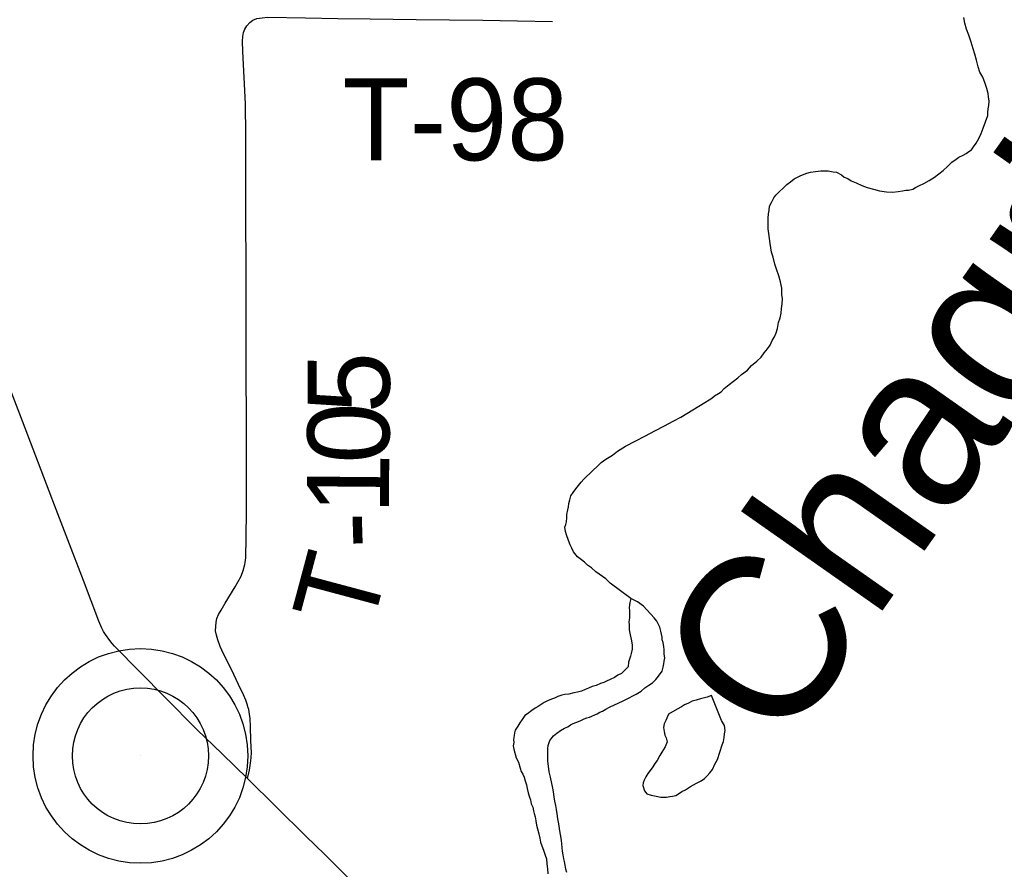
# Model space of a CAD drawing. Extents: x -11.4 to 84.1, y 11.1 to 59.
# Drawn here: x 30.516 to 31.198, y 46.042 to 46.631 of the extents above; entities that cross this region are included whole.
import ezdxf

# ---------------------------------------------------------------- set-up
doc = ezdxf.new("R2010")
doc.units = 0
for name, color, linetype in [('GM_X_County_Road', 7, 'Continuous'), ('GM_X_Major_River', 7, 'Continuous'), ('GM_X_Major_River_Text', 7, 'Continuous'), ('GM_X_Minor_Lake', 7, 'Continuous'), ('GM_X_Township_Road', 7, 'Continuous'), ('GM_X_Township_Road_Text', 7, 'Continuous'), ('GM_X_Unincorporated', 7, 'Continuous'), ('GM_X_Unincorporated_Location', 7, 'Continuous')]:
    doc.layers.add(name, color=color, linetype=linetype)

msp = doc.modelspace()

# ---------------------------------------------------------------- linework, layer by layer
at = {"layer": 'GM_X_County_Road'}
for points in [[(30.53861, 46.29722), (30.5379, 46.29909), (30.5268, 46.32812), (30.51571, 46.35714), (30.50463, 46.38616)], [(30.67345, 46.10475), (30.65588, 46.12173), (30.63832, 46.13872), (30.61646, 46.1608), (30.59888, 46.17856), (30.5813, 46.19632), (30.5796, 46.19824), (30.57799, 46.20026), (30.5751, 46.20449), (30.57377, 46.2067), (30.57259, 46.20897), (30.57056, 46.21368), (30.55977, 46.24187), (30.54898, 46.27007), (30.53861, 46.29722)], [(30.81127, 45.9465), (30.80276, 45.96043), (30.79284, 45.9753), (30.78345, 45.98887), (30.77331, 46.00193), (30.76253, 46.01486), (30.75162, 46.02704), (30.74071, 46.03846), (30.7272, 46.05177), (30.71369, 46.06508), (30.69357, 46.08492), (30.67345, 46.10475)]]:
    msp.add_lwpolyline(points, dxfattribs=at)
at = {"layer": 'GM_X_Major_River'}
for points in [[(31.06089, 46.52418), (31.06353, 46.52499), (31.06694, 46.52542), (31.07073, 46.52586), (31.07567, 46.52594), (31.0791, 46.52524), (31.08139, 46.5249), (31.08483, 46.52305), (31.08676, 46.52156), (31.08943, 46.52046), (31.09174, 46.51898), (31.09518, 46.51752), (31.09901, 46.51568), (31.10283, 46.51422), (31.10703, 46.51315), (31.11123, 46.51208), (31.11618, 46.5114), (31.12036, 46.51109), (31.12415, 46.51153), (31.12718, 46.51196), (31.12945, 46.51238), (31.13135, 46.51241), (31.13438, 46.51322), (31.13626, 46.51439), (31.1389, 46.51557), (31.14191, 46.51714), (31.14567, 46.51911), (31.14943, 46.52145), (31.15243, 46.52378), (31.15543, 46.52611), (31.15843, 46.52882), (31.16141, 46.53191), (31.16442, 46.53386), (31.16629, 46.53542), (31.16931, 46.53661), (31.17119, 46.53778), (31.17306, 46.53933), (31.17494, 46.5405), (31.17643, 46.54243), (31.17828, 46.54512), (31.18013, 46.54819), (31.18159, 46.55164), (31.18305, 46.55546), (31.18632, 46.56426), (31.18629, 46.56617), (31.18662, 46.56883), (31.18696, 46.57112), (31.18729, 46.57417), (31.18686, 46.5772), (31.18644, 46.57948), (31.18563, 46.58289), (31.18443, 46.58629), (31.18283, 46.59083), (31.18088, 46.59422), (31.17968, 46.598), (31.17846, 46.60254), (31.17725, 46.60671), (31.17605, 46.61049), (31.17483, 46.61503), (31.17323, 46.61995), (31.17164, 46.6241), (31.17043, 46.62827), (31.16961, 46.63206)], [(30.93898, 46.22937), (30.92473, 46.24017), (30.92164, 46.24316), (30.91472, 46.24799), (30.91164, 46.2506), (30.90895, 46.25246), (30.90701, 46.25471), (30.90471, 46.25619), (30.90201, 46.25843), (30.8993, 46.26181), (30.89812, 46.26445), (30.89694, 46.26671), (30.89575, 46.26974), (30.89454, 46.27352), (30.89375, 46.27579), (30.89332, 46.27882), (30.89404, 46.28074), (30.89439, 46.28264), (30.89473, 46.28531), (30.89469, 46.28759), (30.89539, 46.29102), (30.89574, 46.29293), (30.89608, 46.29522), (30.89679, 46.29789), (30.89751, 46.30057), (30.89899, 46.30287), (30.90084, 46.30556), (30.90271, 46.30788), (30.90457, 46.31019), (30.90643, 46.31212), (30.9083, 46.31405), (30.91054, 46.31599), (30.91279, 46.31831), (30.91578, 46.32102), (30.91839, 46.32373), (30.92177, 46.32606), (30.92628, 46.3288), (30.92966, 46.33152), (30.93529, 46.33503), (30.94207, 46.33856), (30.94923, 46.3421), (30.95563, 46.34563), (30.9624, 46.34916), (30.96843, 46.35231), (30.9737, 46.35505), (30.9861, 46.36286), (30.99024, 46.36521), (30.99325, 46.36716), (30.99513, 46.36833), (30.997, 46.36988), (30.99963, 46.37145), (31.00151, 46.37262), (31.00375, 46.37494), (31.00713, 46.37766), (31.01013, 46.37999), (31.01313, 46.38232), (31.01575, 46.38464), (31.01987, 46.38775), (31.02248, 46.39084), (31.02622, 46.39394), (31.02922, 46.39665), (31.03145, 46.39973), (31.03368, 46.40243), (31.03553, 46.40512), (31.037, 46.40819), (31.03848, 46.41087), (31.03957, 46.41356), (31.04066, 46.41661), (31.04135, 46.42081), (31.04243, 46.42387), (31.04314, 46.4273), (31.04347, 46.43035), (31.04379, 46.43378), (31.04411, 46.4372), (31.04368, 46.44024), (31.04361, 46.44442), (31.04278, 46.44897), (31.04157, 46.45313), (31.03997, 46.45767), (31.03877, 46.46107), (31.03755, 46.466), (31.03636, 46.4694), (31.03593, 46.47243), (31.0355, 46.47547), (31.03506, 46.47888), (31.03462, 46.4823), (31.03418, 46.48571), (31.03413, 46.48914), (31.03406, 46.49294), (31.03439, 46.49599), (31.03473, 46.49827), (31.03506, 46.50132), (31.03654, 46.50401), (31.038, 46.50707), (31.03949, 46.509), (31.04696, 46.51635), (31.04959, 46.51829), (31.05222, 46.52024), (31.05485, 46.5218), (31.05673, 46.52259), (31.06089, 46.52418)], [(30.89467, 46.03966), (30.89387, 46.04193), (30.89344, 46.04458), (30.89302, 46.04724), (30.89261, 46.04913), (30.89218, 46.05179), (30.89176, 46.05444), (30.89134, 46.05672), (30.8913, 46.05938), (30.89088, 46.06165), (30.89045, 46.06469), (30.89003, 46.06696), (30.8896, 46.07), (30.88916, 46.07341), (30.88835, 46.07682), (30.88791, 46.08024), (30.88748, 46.08327), (30.88705, 46.08592), (30.88624, 46.08895), (30.88581, 46.09199), (30.88537, 46.09541), (30.88495, 46.09806), (30.8833, 46.10564), (30.88289, 46.10753), (30.88248, 46.10943), (30.88204, 46.11322), (30.8816, 46.11664), (30.88156, 46.1193), (30.8815, 46.12234), (30.88146, 46.12538), (30.8818, 46.12767), (30.88288, 46.13111), (30.88548, 46.13419), (30.88773, 46.13613), (30.89036, 46.13808), (30.89299, 46.13964), (30.89525, 46.14044), (30.89713, 46.14199), (30.89901, 46.14278), (30.9009, 46.14357), (30.90392, 46.14476), (30.90656, 46.14595), (30.90844, 46.14674), (30.91034, 46.14715), (30.91561, 46.14952), (30.91749, 46.15069), (30.91938, 46.15148), (30.92164, 46.15266), (30.92427, 46.15422), (30.93369, 46.15856), (30.93558, 46.15935), (30.93784, 46.16053), (30.94047, 46.16209), (30.94273, 46.16327), (30.94611, 46.16523), (30.94874, 46.16755), (30.95136, 46.1695), (30.954, 46.17106), (30.95624, 46.17338), (30.9581, 46.17569), (30.9607, 46.17916), (30.96141, 46.18183), (30.96175, 46.18412), (30.9621, 46.18602), (30.96244, 46.18831), (30.96202, 46.19097), (30.96197, 46.19401), (30.96193, 46.19591), (30.9615, 46.19895), (30.96071, 46.20083), (30.96068, 46.20273), (30.96027, 46.20463), (30.95985, 46.2069), (30.95905, 46.20955), (30.95826, 46.21144), (30.95708, 46.2137), (30.95514, 46.21595), (30.94779, 46.2242), (30.94356, 46.22717), (30.94087, 46.22865), (30.93898, 46.22937)], [(30.93898, 46.22937), (30.93825, 46.2267), (30.93793, 46.22327), (30.93797, 46.22099), (30.93801, 46.21833), (30.93805, 46.21605), (30.93771, 46.21338), (30.93775, 46.2111), (30.93781, 46.20768), (30.93862, 46.20427), (30.93945, 46.2001), (30.93989, 46.19707), (30.93993, 46.19441), (30.93922, 46.19135), (30.93887, 46.18945), (30.93815, 46.18753), (30.93743, 46.18524), (30.9371, 46.18219), (30.93523, 46.18026), (30.93261, 46.17756)], [(30.93261, 46.17756), (30.92998, 46.17637), (30.92772, 46.17481), (30.92471, 46.17324), (30.92207, 46.17206), (30.92019, 46.17127), (30.91792, 46.17047), (30.9149, 46.16928), (30.91226, 46.16848), (30.90962, 46.16729), (30.90735, 46.16649), (30.90472, 46.16531), (30.90207, 46.16451), (30.89942, 46.16408), (30.89601, 46.16327), (30.89336, 46.16284), (30.89109, 46.16242), (30.88844, 46.16162), (30.88618, 46.16044), (30.88392, 46.15965), (30.88128, 46.15846), (30.87902, 46.15728), (30.87489, 46.15455), (30.87263, 46.15338), (30.87038, 46.15182), (30.86738, 46.14949), (30.8655, 46.14832), (30.86364, 46.14562), (30.86216, 46.14332), (30.86068, 46.14101), (30.85883, 46.13832), (30.85848, 46.13641), (30.85813, 46.13451), (30.8578, 46.13184), (30.85783, 46.12956), (30.85749, 46.12727), (30.85791, 46.12499), (30.85953, 46.11894), (30.8611, 46.11592), (30.86231, 46.11176), (30.86311, 46.10949), (30.86428, 46.10761), (30.86507, 46.10572), (30.86588, 46.10307), (30.86668, 46.10042), (30.86711, 46.09777), (30.86791, 46.09474), (30.86872, 46.09171), (30.86952, 46.08982), (30.86994, 46.08717), (30.87112, 46.0849), (30.87154, 46.08225), (30.87195, 46.08035), (30.87275, 46.07809), (30.87318, 46.07543), (30.87361, 46.0724), (30.87441, 46.06975), (30.87523, 46.06634), (30.87604, 46.06331), (30.87646, 46.06065), (30.87727, 46.05801), (30.87846, 46.05498), (30.87965, 46.05158), (30.88046, 46.04893), (30.8809, 46.04552), (30.88133, 46.0421), (30.88139, 46.03868)]]:
    msp.add_lwpolyline(points, dxfattribs=at)
at = {"layer": 'GM_X_Minor_Lake'}
for points in [[(30.94721, 46.09984), (30.94842, 46.09606), (30.94997, 46.09418), (30.95302, 46.09309), (30.95645, 46.09239), (30.95988, 46.09168), (30.96368, 46.09175), (30.96595, 46.09216), (30.96785, 46.09257), (30.97012, 46.09299), (30.972, 46.09417), (30.97425, 46.09572), (30.97689, 46.09691), (30.98027, 46.09924), (30.9844, 46.10159), (30.9878, 46.10317), (30.99005, 46.10473), (30.99192, 46.10666), (30.99378, 46.10859), (30.99565, 46.1109), (30.9971, 46.11473), (30.99895, 46.1178), (31.00219, 46.12812), (31.00329, 46.13042), (31.00363, 46.13309), (31.00397, 46.13576), (31.00431, 46.13805), (31.00387, 46.14146), (31.00191, 46.14485), (30.99479, 46.16223)], [(30.99479, 46.16223), (30.99176, 46.16103), (30.98723, 46.15982), (30.9842, 46.15901), (30.98156, 46.15821), (30.97892, 46.15702), (30.97628, 46.15584), (30.97403, 46.15428), (30.97101, 46.15271), (30.965, 46.14919), (30.96317, 46.14498), (30.96207, 46.14267), (30.96173, 46.14001), (30.96216, 46.13735), (30.96258, 46.1347), (30.96337, 46.13281), (30.96418, 46.13016), (30.96272, 46.12671), (30.96161, 46.1248), (30.9605, 46.12288), (30.95902, 46.12057), (30.95718, 46.11712), (30.95569, 46.11519), (30.95421, 46.11289), (30.95236, 46.11019), (30.95087, 46.10827), (30.94939, 46.10596), (30.94829, 46.10366), (30.94756, 46.10175), (30.94721, 46.09984)], [(30.99479, 46.16223), (30.99176, 46.16103), (30.98723, 46.15982), (30.9842, 46.15901), (30.98156, 46.15821), (30.97892, 46.15702), (30.97628, 46.15584), (30.97403, 46.15428), (30.97101, 46.15271), (30.965, 46.14919), (30.96317, 46.14498), (30.96207, 46.14267), (30.96173, 46.14001), (30.96216, 46.13735), (30.96258, 46.1347), (30.96337, 46.13281), (30.96418, 46.13016), (30.96272, 46.12671), (30.96161, 46.1248), (30.9605, 46.12288), (30.95902, 46.12057), (30.95718, 46.11712), (30.95569, 46.11519), (30.95421, 46.11289), (30.95236, 46.11019), (30.95087, 46.10827), (30.94939, 46.10596), (30.94829, 46.10366), (30.94756, 46.10175), (30.94721, 46.09984), (30.94842, 46.09606), (30.94997, 46.09418), (30.95302, 46.09309), (30.95645, 46.09239), (30.95988, 46.09168), (30.96368, 46.09175), (30.96595, 46.09216), (30.96785, 46.09257), (30.97012, 46.09299), (30.972, 46.09417), (30.97425, 46.09572), (30.97689, 46.09691), (30.98027, 46.09924), (30.9844, 46.10159), (30.9878, 46.10317), (30.99005, 46.10473), (30.99192, 46.10666), (30.99378, 46.10859), (30.99565, 46.1109), (30.9971, 46.11473), (30.99895, 46.1178), (31.00219, 46.12812), (31.00329, 46.13042), (31.00363, 46.13309), (31.00397, 46.13576), (31.00431, 46.13805), (31.00387, 46.14146), (31.00191, 46.14485), (30.99479, 46.16223)]]:
    msp.add_lwpolyline(points, dxfattribs=at)
at = {"layer": 'GM_X_Township_Road'}
for points in [[(30.66904, 46.24486), (30.67047, 46.24875), (30.67161, 46.25306), (30.67191, 46.25433), (30.67217, 46.25755), (30.67238, 46.26229), (30.67255, 46.2672), (30.67267, 46.29456), (30.67281, 46.31643), (30.67239, 46.52948), (30.67225, 46.55089), (30.6721, 46.57231), (30.67114, 46.59048), (30.67018, 46.60866), (30.66998, 46.61566), (30.67019, 46.61904), (30.67061, 46.62169), (30.67153, 46.62408), (30.67305, 46.62636), (30.67514, 46.62865)], [(30.67514, 46.62865), (30.67723, 46.63026), (30.67999, 46.63131), (30.68361, 46.63198), (30.6876, 46.63226), (30.71373, 46.63184), (30.73611, 46.63146), (30.7585, 46.63107), (30.77442, 46.63095), (30.79033, 46.63082), (30.81336, 46.63053), (30.83638, 46.63024), (30.86054, 46.62983), (30.88469, 46.62942)], [(30.53861, 46.29722), (30.5379, 46.29909), (30.5268, 46.32812), (30.51571, 46.35714), (30.50463, 46.38616)], [(30.67345, 46.10475), (30.65588, 46.12173), (30.63832, 46.13872), (30.61646, 46.1608), (30.59888, 46.17856), (30.5813, 46.19632), (30.5796, 46.19824), (30.57799, 46.20026), (30.5751, 46.20449), (30.57377, 46.2067), (30.57259, 46.20897), (30.57056, 46.21368), (30.55977, 46.24187), (30.54898, 46.27007), (30.53861, 46.29722)], [(30.67378, 46.15437), (30.67342, 46.15558), (30.67217, 46.15898), (30.67056, 46.16264), (30.66717, 46.16988), (30.66234, 46.18025), (30.6568, 46.19106), (30.65457, 46.19624), (30.65296, 46.2008), (30.65197, 46.20402), (30.65138, 46.2071), (30.65171, 46.21296), (30.65225, 46.21555), (30.65341, 46.21832), (30.6551, 46.22126), (30.65785, 46.22612), (30.66493, 46.23745), (30.66904, 46.24486)], [(30.67345, 46.10475), (30.67476, 46.11045), (30.6756, 46.11527), (30.67593, 46.11894), (30.67611, 46.1227), (30.67586, 46.13075), (30.67552, 46.14066), (30.67521, 46.1462), (30.67485, 46.1494), (30.67432, 46.15254), (30.67378, 46.15437)], [(30.81127, 45.9465), (30.80276, 45.96043), (30.79284, 45.9753), (30.78345, 45.98887), (30.77331, 46.00193), (30.76253, 46.01486), (30.75162, 46.02704), (30.74071, 46.03846), (30.7272, 46.05177), (30.71369, 46.06508), (30.69357, 46.08492), (30.67345, 46.10475)]]:
    msp.add_lwpolyline(points, dxfattribs=at)
at = {"layer": 'GM_X_Unincorporated'}
for radius in [0.0744, 0.04716]:
    msp.add_circle((30.59925, 46.12037), radius, dxfattribs=at)
at = {"layer": 'GM_X_Unincorporated_Location'}
msp.add_line((30.59925, 46.12037), (30.59925, 46.12037), dxfattribs=at)

# ---------------------------------------------------------------- texts
at = {"layer": 'GM_X_Major_River_Text'}
msp.add_text('Chagrin', height=0.113712, rotation=54.89589, dxfattribs=at).set_placement((31.04412, 46.12259))
at = {"layer": 'GM_X_Township_Road_Text'}
for s, height, rotation, p in [('T-98', 0.056818, 0.00001, (30.73937, 46.5331)), ('5', 0.05682, 89.66747, (30.77184, 46.35784)), ('0', 0.05682, 89.63452, (30.77162, 46.3228)), ('1', 0.05682, 89.50042, (30.77131, 46.28766)), ('-', 0.05682, 91.79927, (30.77203, 46.26494)), ('T', 0.05682, 75.02303, (30.75898, 46.20593))]:
    msp.add_text(s, height=height, rotation=rotation, dxfattribs=at).set_placement(p)

doc.saveas('drawing.dxf')
